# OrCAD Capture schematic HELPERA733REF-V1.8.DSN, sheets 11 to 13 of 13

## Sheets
11 07 M.2 key M Slot/4G: size B; note: M.2 key M Slot/4G
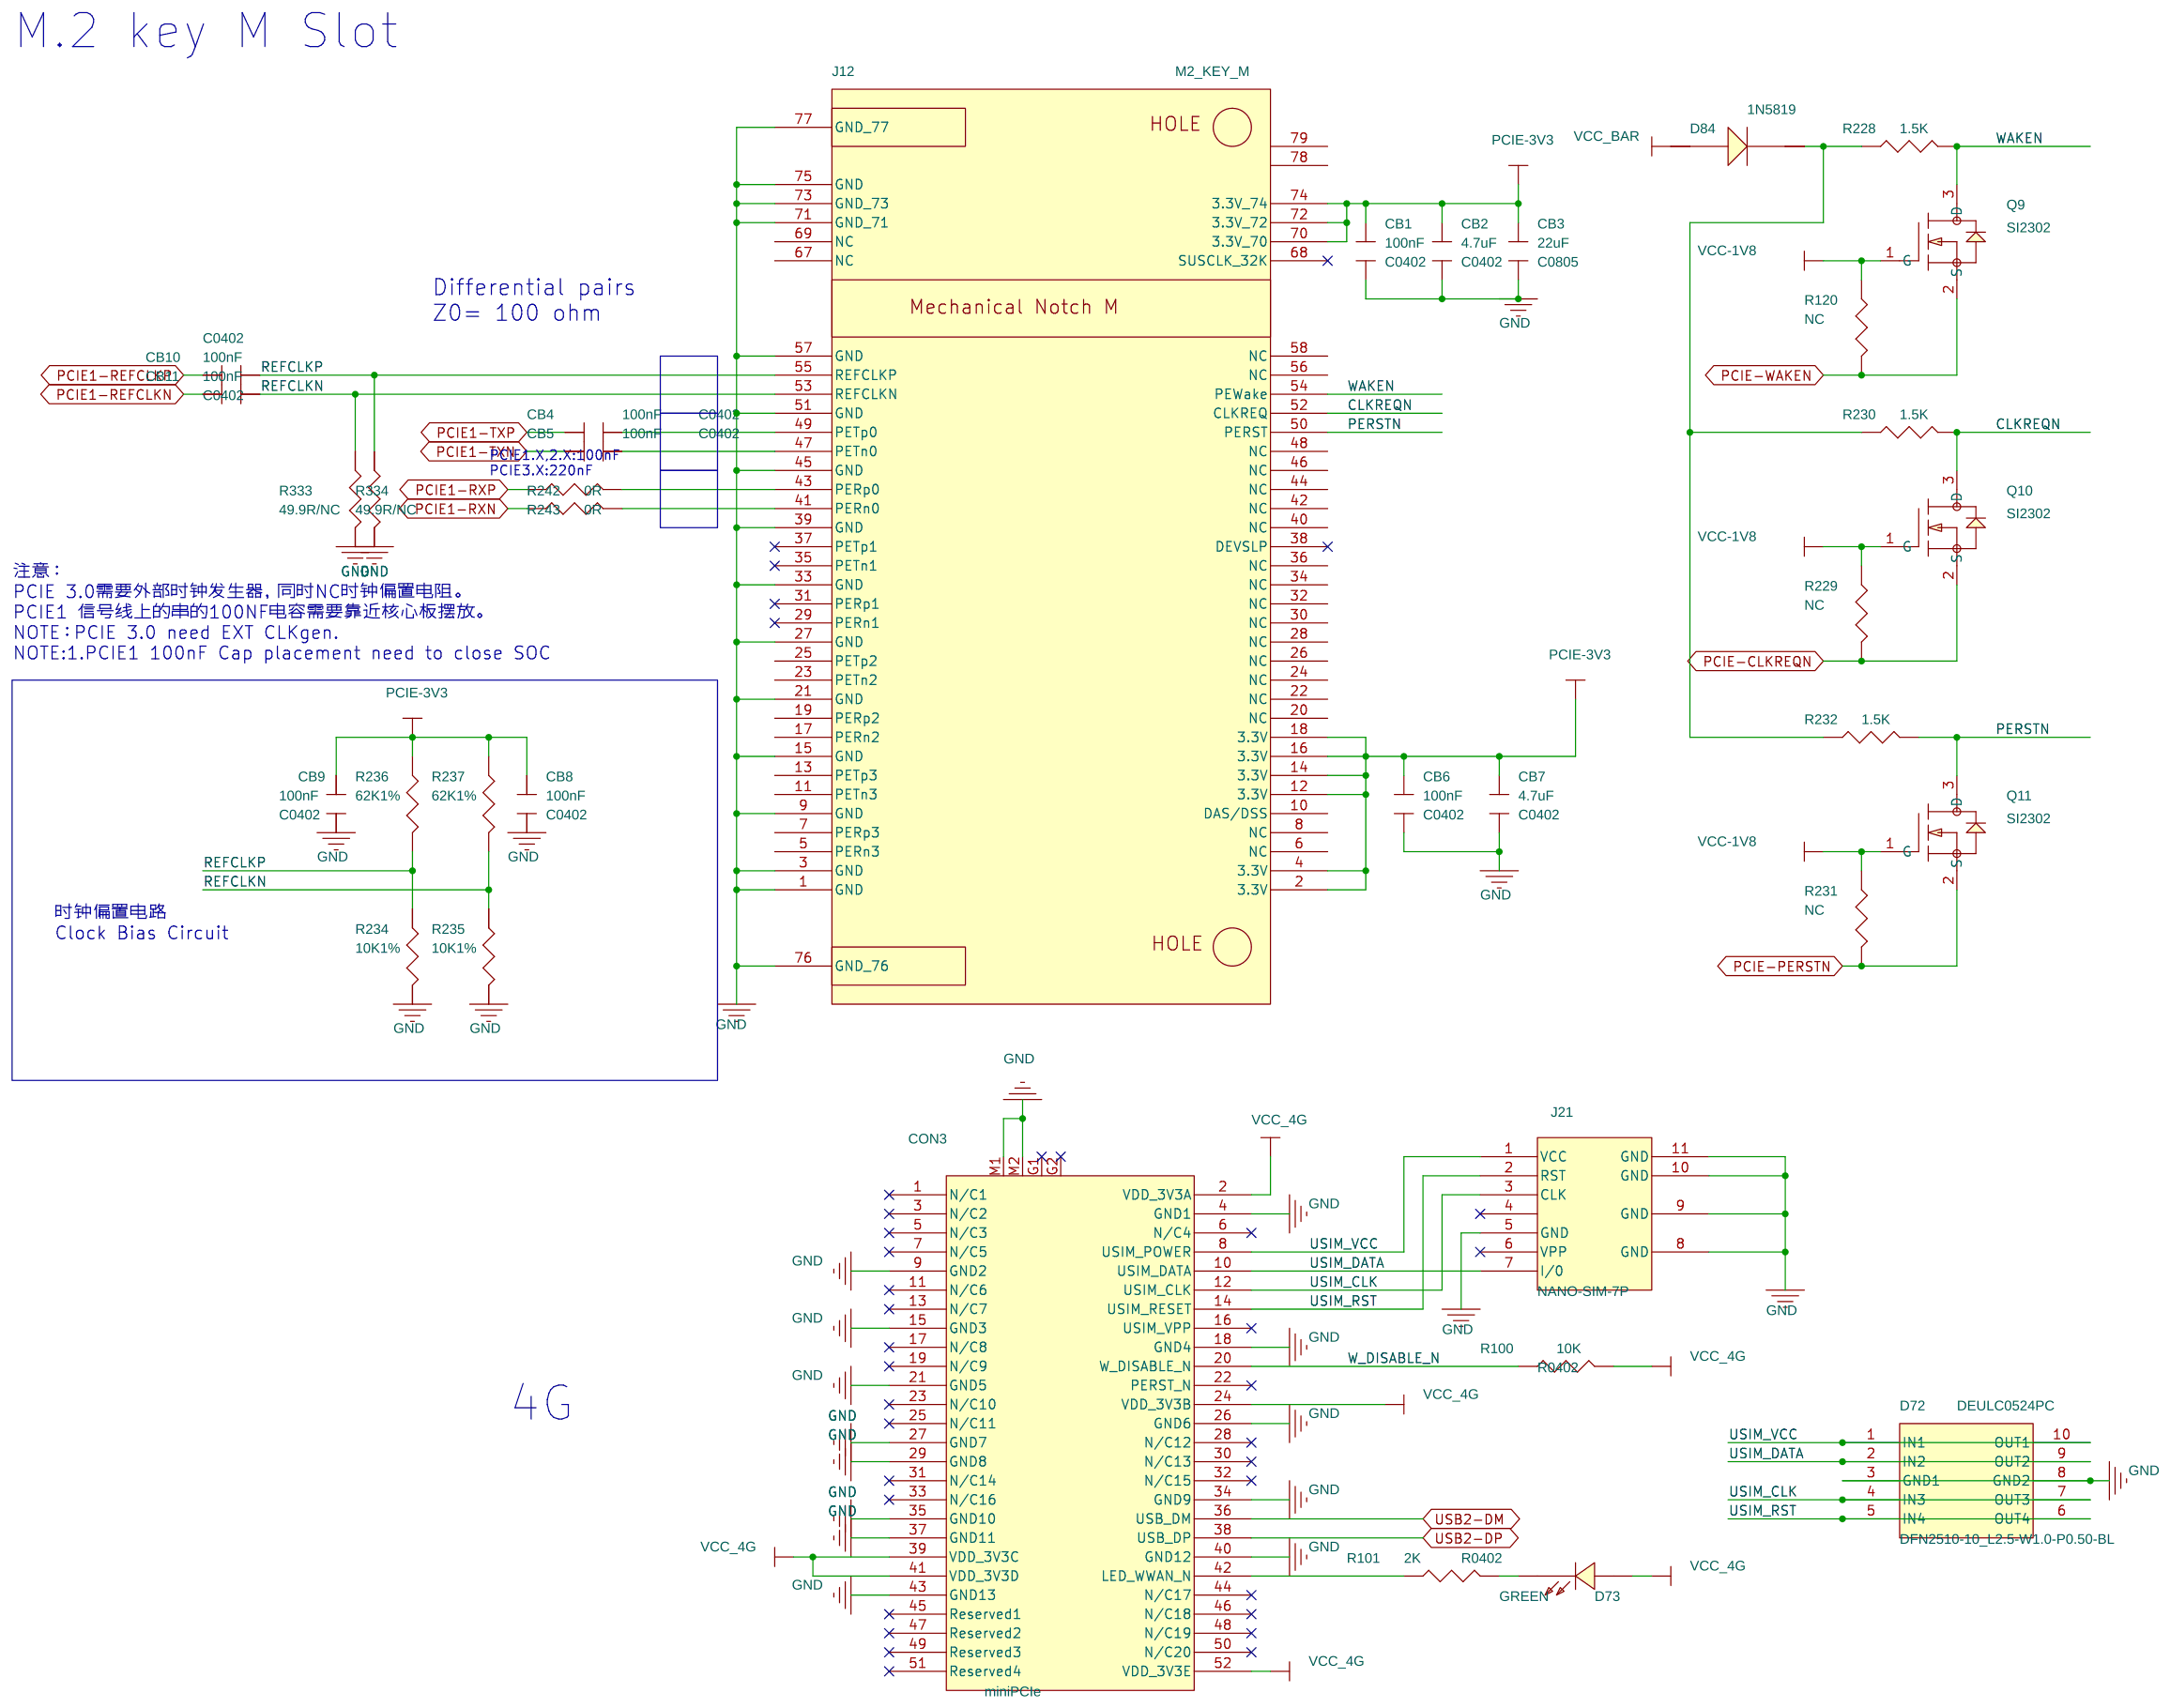
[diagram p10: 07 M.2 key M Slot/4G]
12 11 OTG/host/HUB: size B; note: OTG/host/HUB
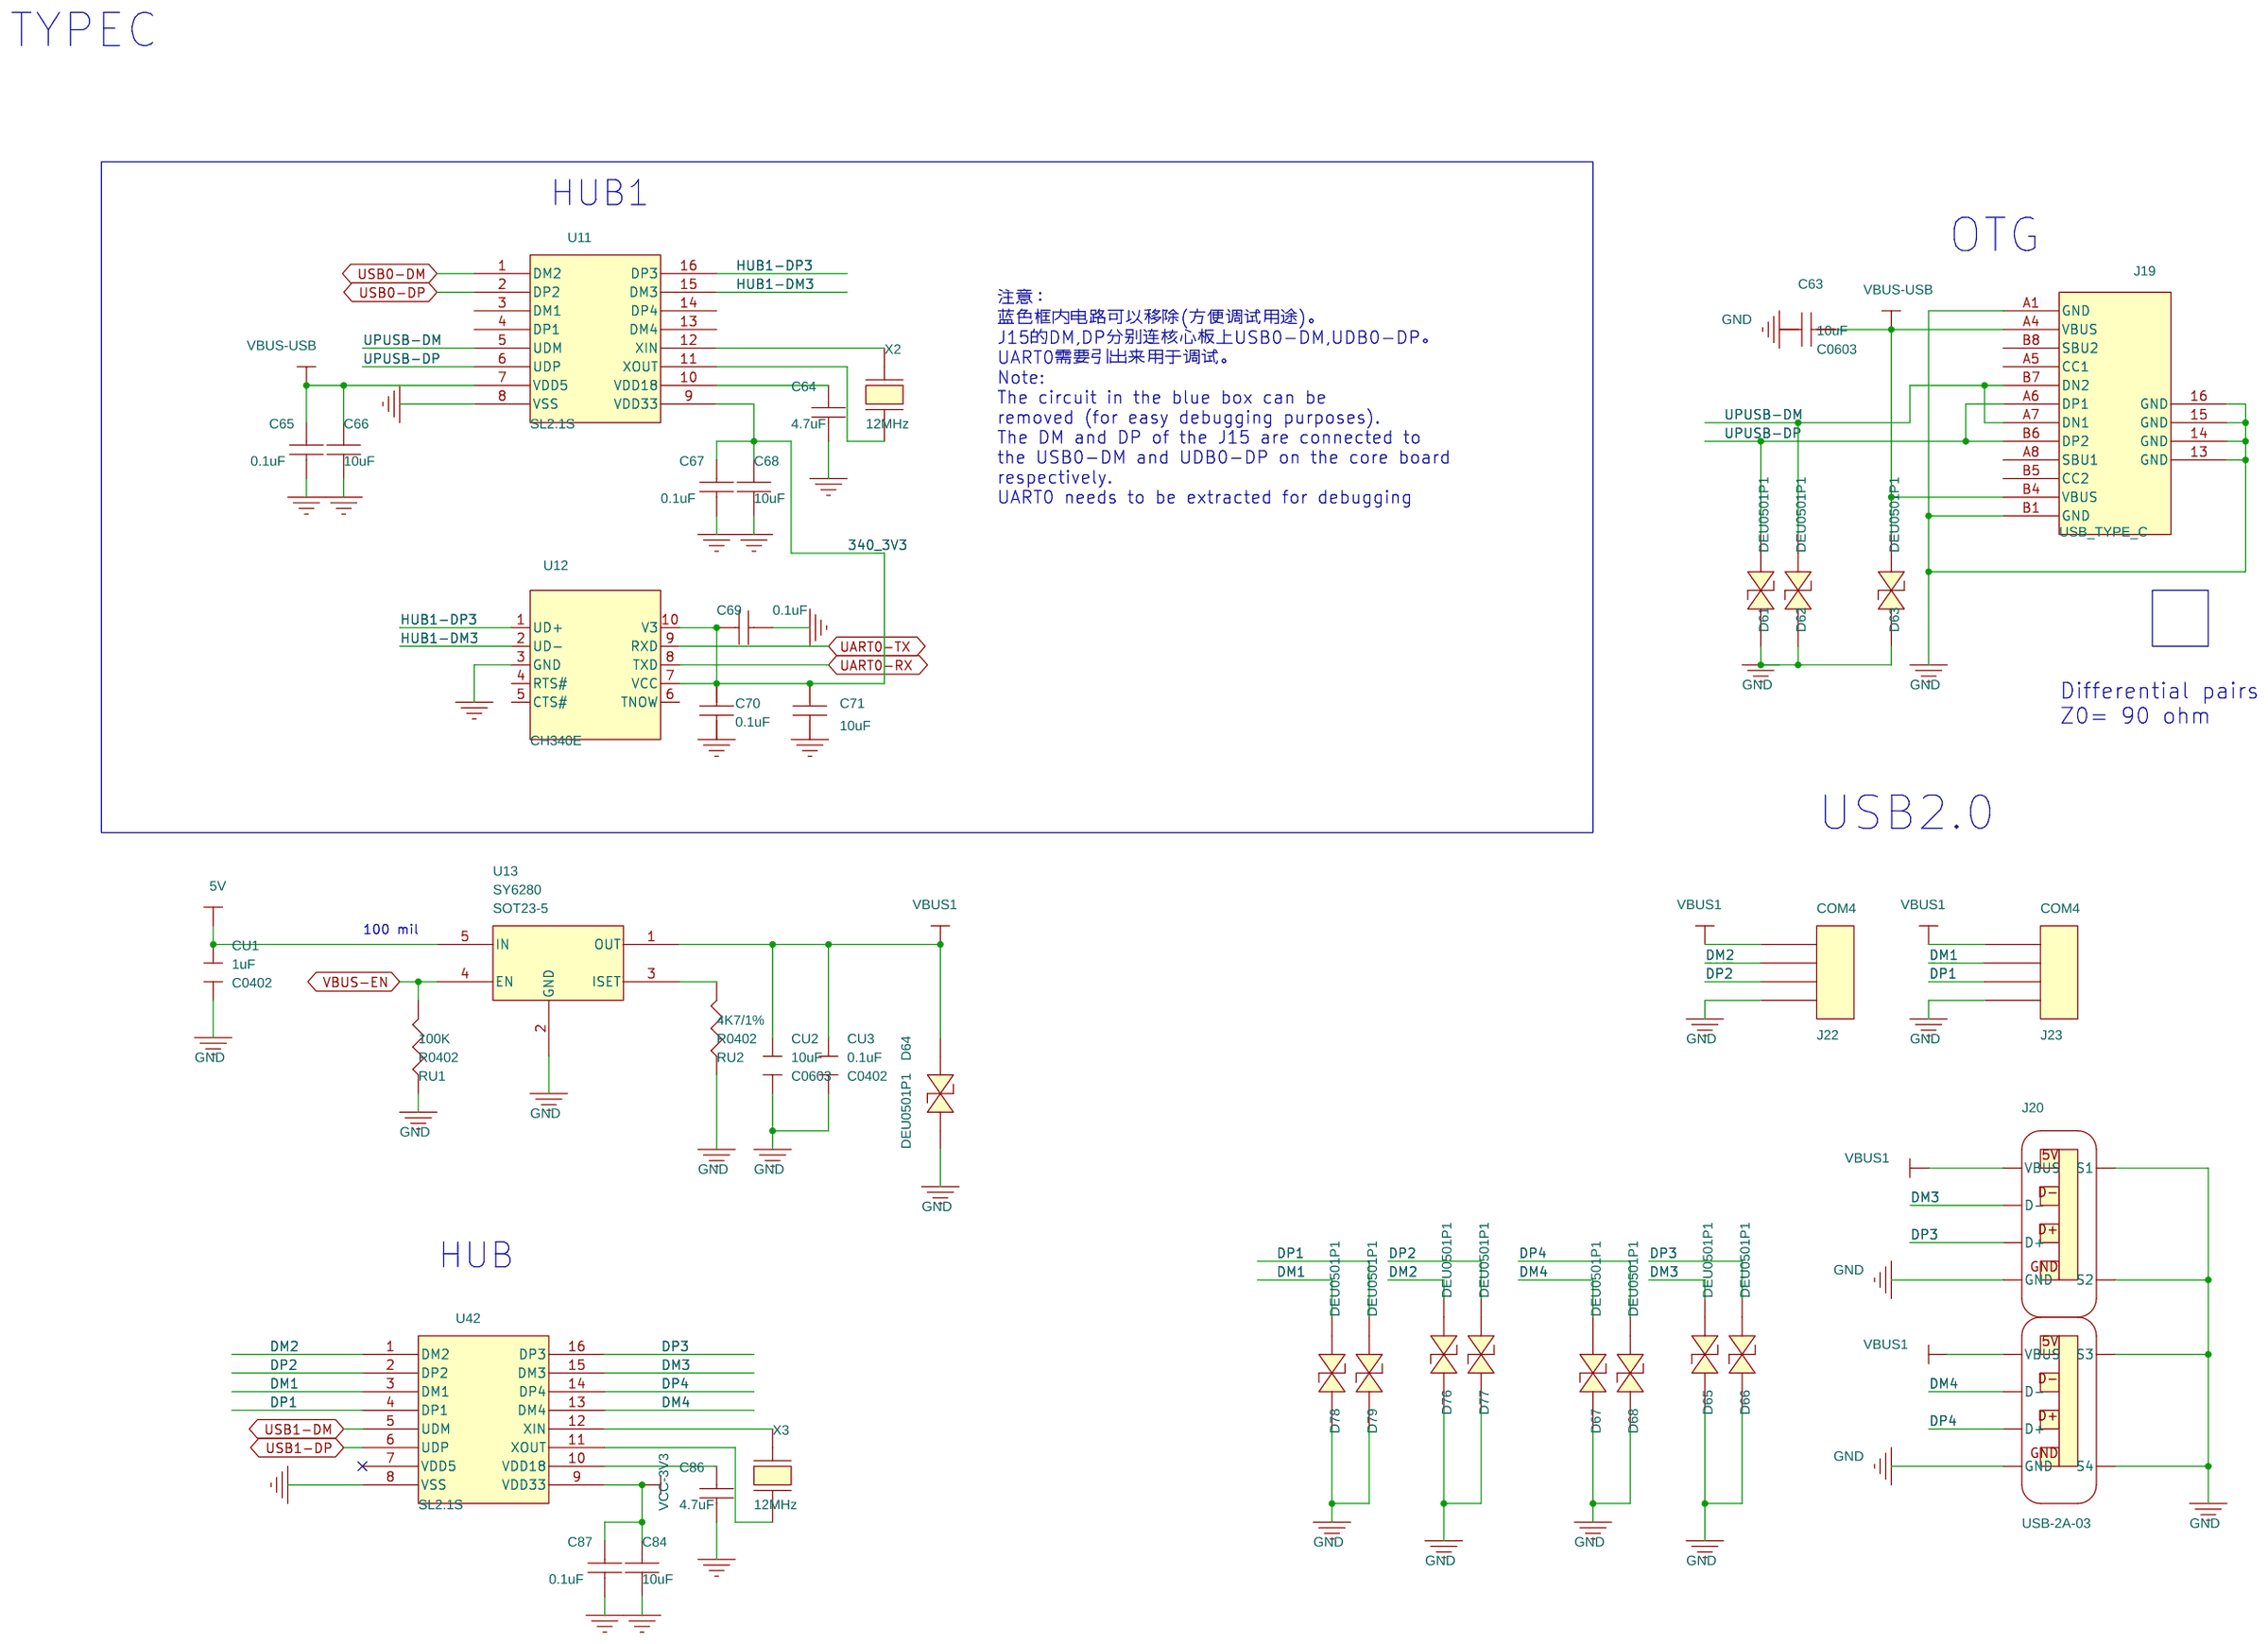
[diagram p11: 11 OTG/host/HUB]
13 06 AUDIO AC101/AC101B: size C; note: AUDIO AC101/AC101B
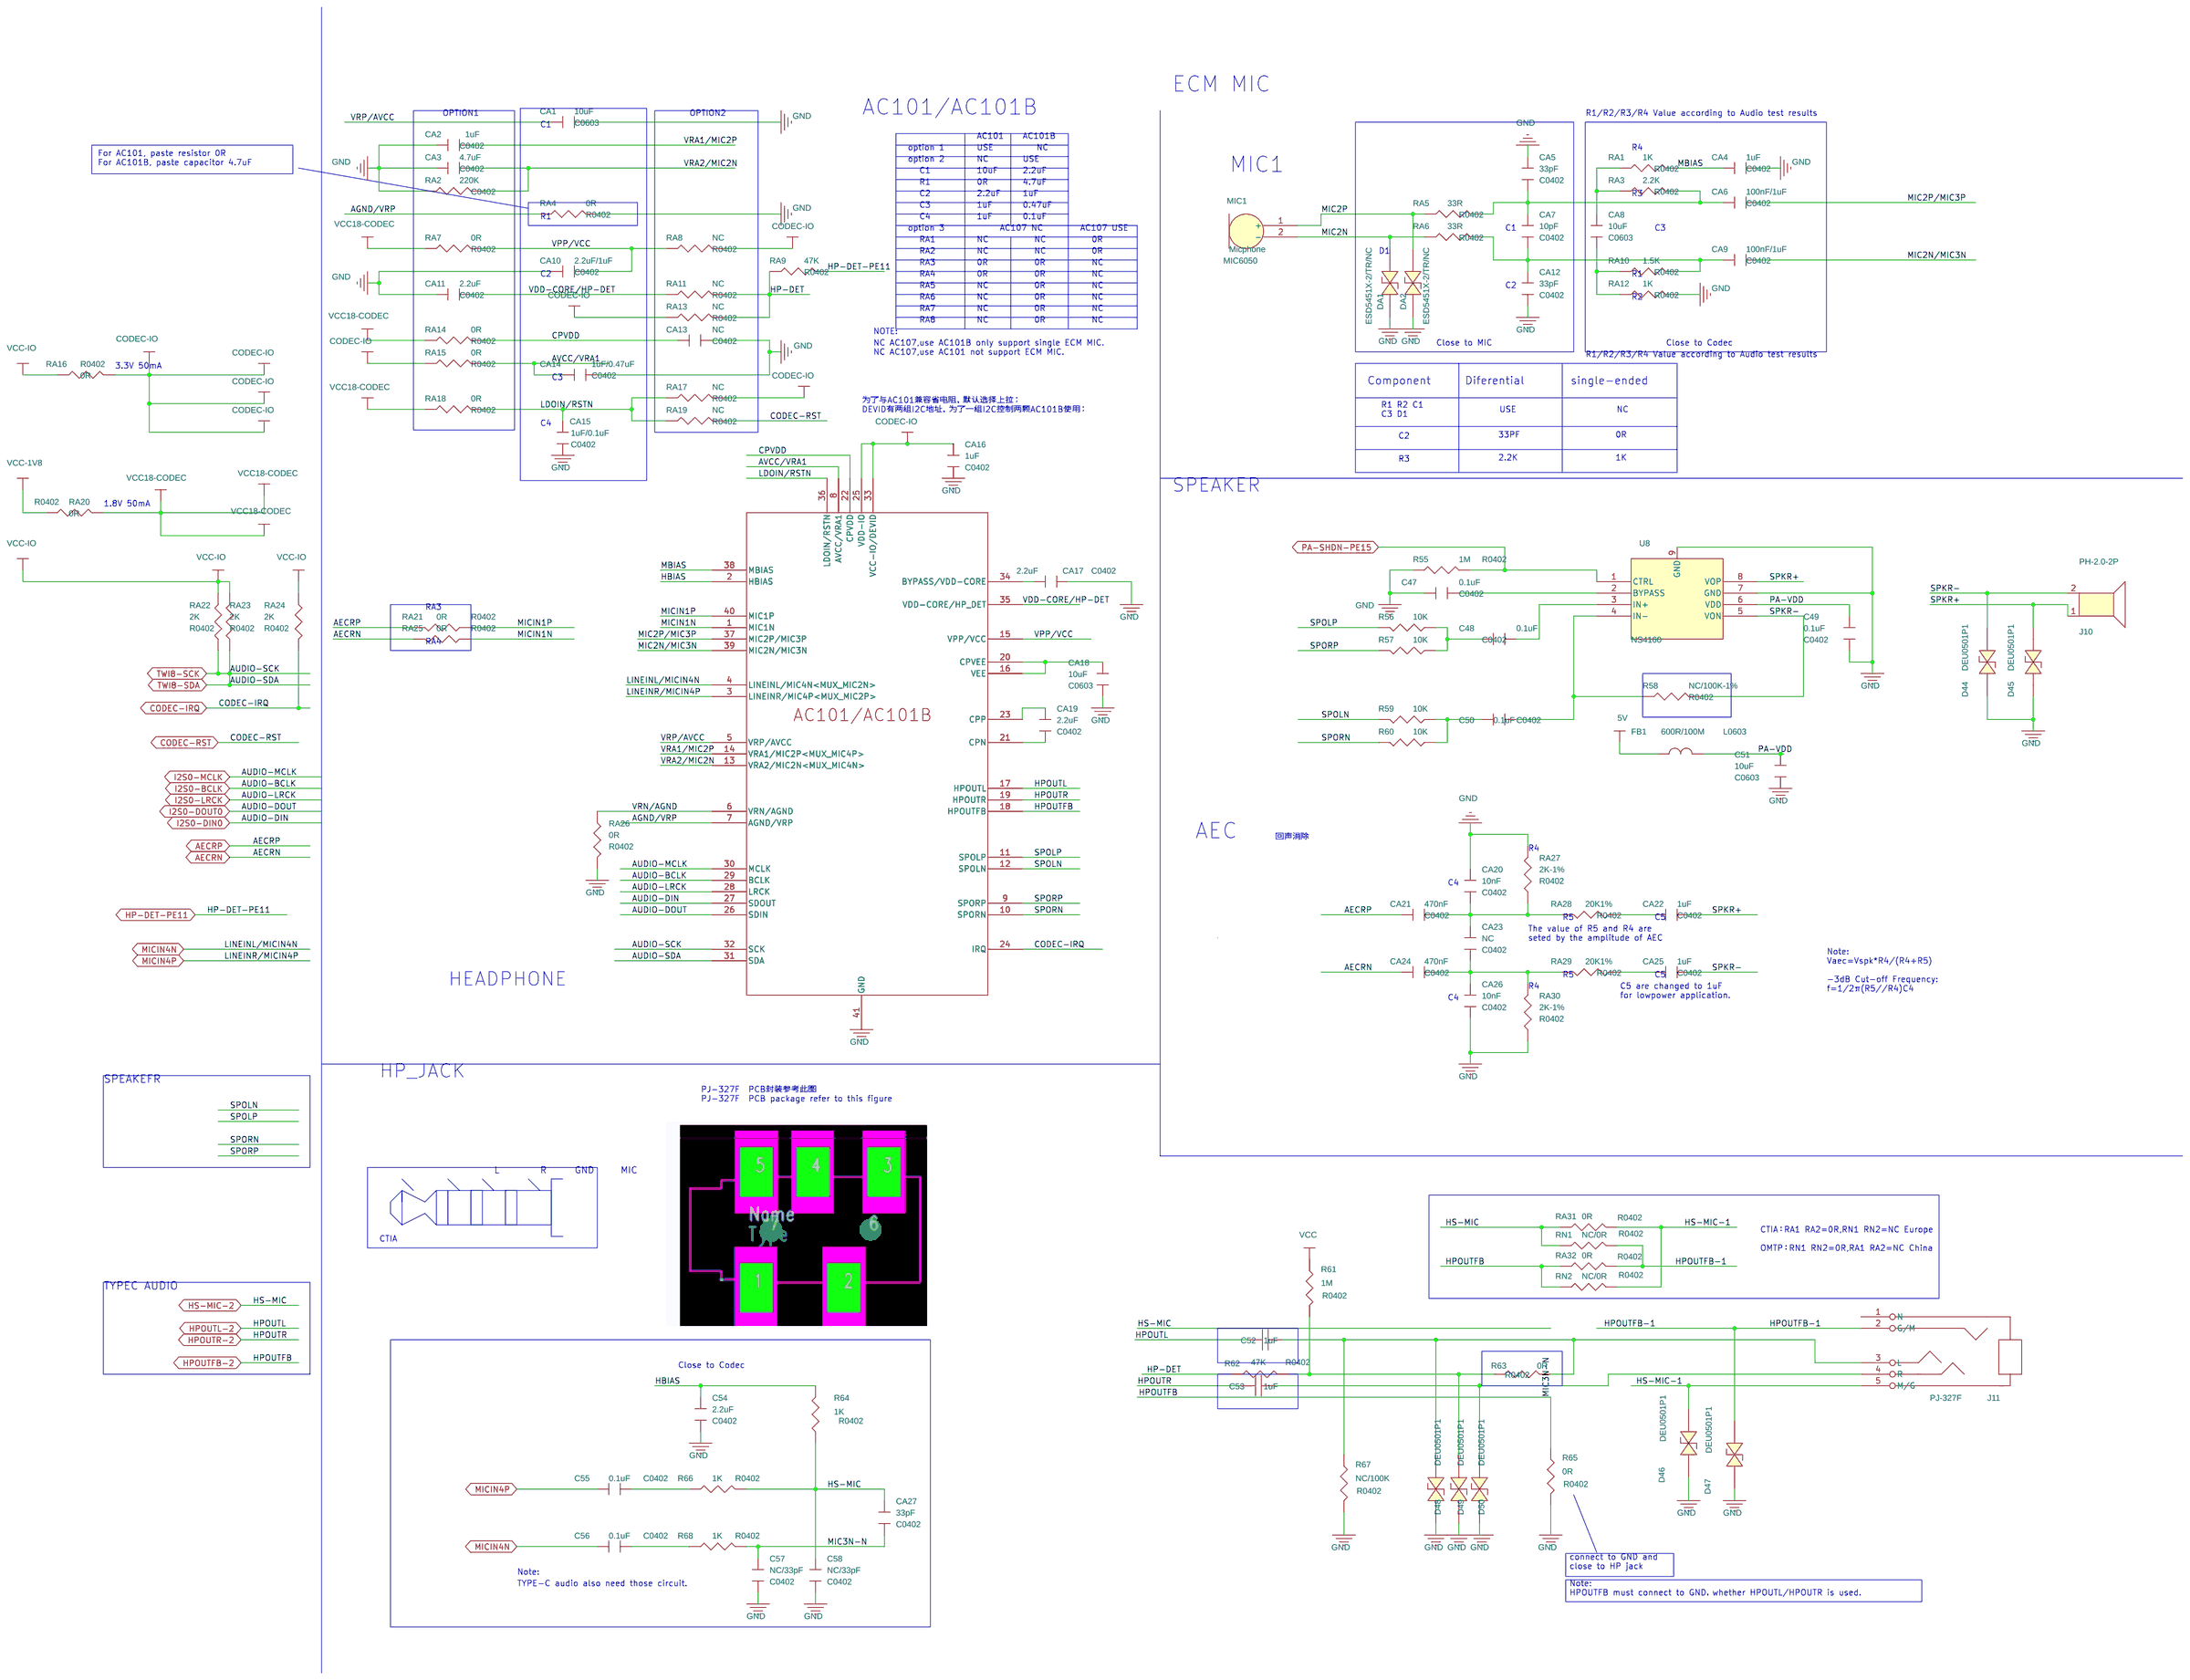
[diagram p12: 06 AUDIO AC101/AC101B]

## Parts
sheet 06 AUDIO AC101/AC101B
C47  0.1uF  [C0402]
C48  0.1uF  [C0402]
C49  0.1uF  [C0402]
C50  0.1uF  [C0402]
C51  10uF  [C0603]
C52  1uF  [C0402]
C53  1uF  [C0402]
C54  2.2uF  [C0402]
C55  0.1uF  [C0402]
C56  0.1uF  [C0402]
C57  NC/33pF  [C0402]
C58  NC/33pF  [C0402]
CA1  10uF  [C0603]
CA2  1uF  [C0402]
CA3  4.7uF  [C0402]
CA4  1uF  [C0402]
CA5  33pF  [C0402]
CA6  100nF/1uF  [C0402]
CA7  10pF  [C0402]
CA8  10uF  [C0603]
CA9  100nF/1uF  [C0402]
CA10  2.2uF/1uF  [C0402]
CA11  2.2uF  [C0402]
CA12  33pF  [C0402]
CA13  NC  [C0402]
CA14  1uF/0.47uF  [C0402]
CA15  1uF/0.1uF  [C0402]
CA16  1uF  [C0402]
CA17  2.2uF  [C0402]
CA18  10uF  [C0603]
CA19  2.2uF  [C0402]
CA20  10nF  [C0402]
CA21  470nF  [C0402]
CA22  1uF  [C0402]
CA23  NC  [C0402]
CA24  470nF  [C0402]
CA25  1uF  [C0402]
CA26  10nF  [C0402]
CA27  33pF  [C0402]
D44  DEU0501P1  [ESD0402]
D45  DEU0501P1  [ESD0402]
D46  DEU0501P1  [ESD0402]
D47  DEU0501P1  [ESD0402]
D48  DEU0501P1  [ESD0402]
D49  DEU0501P1  [ESD0402]
D50  DEU0501P1  [ESD0402]
DA1  ESD5451X-2/TR/NC  [ESD0402]
DA2  ESD5451X-2/TR/NC  [ESD0402]
FB1  600R/100M  [L0603]
J10  PH-2.0-2P  [PH-2.0-2P]
J11  PJ-327F  [PJ327F]
MIC1  Micphone  [MIC6050]
R55  1M  [R0402]
R56  10K  [R0402]
R57  10K  [R0402]
R58  NC/100K-1%  [R0402]
R59  10K  [R0402]
R60  10K  [R0402]
R61  1M  [R0402]
R62  47K  [R0402]
R63  0R  [R0402]
R64  1K  [R0402]
R65  0R  [R0402]
R66  1K  [R0402]
R67  NC/100K  [R0402]
R68  1K  [R0402]
RA1  1K  [R0402]
RA2  220K  [C0402]
RA3  2.2K  [R0402]
RA4  0R  [R0402]
RA5  33R  [R0402]
RA6  33R  [R0402]
RA7  0R  [R0402]
RA8  NC  [R0402]
RA9  47K  [R0402]
RA10  1.5K  [R0402]
RA11  NC  [R0402]
RA12  1K  [R0402]
RA13  NC  [R0402]
RA14  0R  [R0402]
RA15  0R  [R0402]
RA16  0R  [R0402]
RA17  NC  [R0402]
RA18  0R  [R0402]
RA19  NC  [R0402]
RA20  0R  [R0402]
RA21  0R  [R0402]
RA22  2K  [R0402]
RA23  2K  [R0402]
RA24  2K  [R0402]
RA25  0R  [R0402]
RA26  0R  [R0402]
RA27  2K-1%  [R0402]
RA28  20K1%  [R0402]
RA29  20K1%  [R0402]
RA30  2K-1%  [R0402]
RA31  0R  [R0402]
RA32  0R  [R0402]
RN1  NC/0R  [R0402]
RN2  NC/0R  [R0402]
U8  NS4160  [ESOP-8]
UA1  AC101  [QFN40]
sheet 07 M.2 key M Slot/4G
CB1  100nF  [C0402]
CB2  4.7uF  [C0402]
CB3  22uF  [C0805]
CB4  100nF  [C0402]
CB5  100nF  [C0402]
CB6  100nF  [C0402]
CB7  4.7uF  [C0402]
CB8  100nF  [C0402]
CB9  100nF  [C0402]
CB10  100nF  [C0402]
CB11  100nF  [C0402]
CON3  miniPCIe  [MINI_PCIEX1-52P-5.2H]
D72  DEULC0524PC  [DFN2510-10_L2.5-W1.0-P0.50-BL]
D73  GREEN  [D0603]
D84  1N5819  [SOD323]
J12  M2_KEY_M  [M.2-M-KEY]
J21  NANO-SIM-7P  [NANO-SIM-7P]
Q9  SI2302  [SOT23]
Q10  SI2302  [SOT23]
Q11  SI2302  [SOT23]
R100  10K  [R0402]
R101  2K  [R0402]
R120  NC  [R0402]
R228  1.5K  [R0402]
R229  NC  [R0402]
R230  1.5K  [R0402]
R231  NC  [R0402]
R232  1.5K  [R0402]
R234  10K1%  [R0402]
R235  10K1%  [R0402]
R236  62K1%  [R0402]
R237  62K1%  [R0402]
R242  0R  [R0402]
R243  0R  [R0402]
R333  49.9R/NC  [R0402]
R334  49.9R/NC  [R0402]
sheet 11 OTG/host/HUB
C63  10uF  [C0603]
C64  4.7uF  [C0402]
C65  0.1uF  [C0402]
C66  10uF  [C0603]
C67  0.1uF  [C0402]
C68  10uF  [C0603]
C69  0.1uF  [C0402]
C70  0.1uF  [C0402]
C71  10uF  [C0603]
C84  10uF  [C0603]
C86  4.7uF  [C0402]
C87  0.1uF  [C0402]
CU1  1uF  [C0402]
CU2  10uF  [C0603]
CU3  0.1uF  [C0402]
D61  DEU0501P1  [ESD0402]
D62  DEU0501P1  [ESD0402]
D63  DEU0501P1  [ESD0402]
D64  DEU0501P1  [ESD0402]
D65  DEU0501P1  [ESD0402]
D66  DEU0501P1  [ESD0402]
D67  DEU0501P1  [ESD0402]
D68  DEU0501P1  [ESD0402]
D76  DEU0501P1  [ESD0402]
D77  DEU0501P1  [ESD0402]
D78  DEU0501P1  [ESD0402]
D79  DEU0501P1  [ESD0402]
J19  USB_TYPE_C  [USB_C]
J20  USB-2A-03  [USB-2A-03]
J22  COM4  [PH-2.0-4P]
J23  COM4  [PH-2.0-4P]
RU1  100K  [R0402]
RU2  4K7/1%  [R0402]
U11  SL2.1S  [SSOP16_SL2.1S]
U12  CH340E  [MSOP-10]
U13  SY6280  [SOT23-5]
U42  SL2.1S  [SSOP16_SL2.1S]
X2  12MHz  [X3225]
X3  12MHz  [X3225]

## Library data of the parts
C47-C49 C51 = C-C0402
C50 = CAPACITOR_0: options: 4890-2
C52 C53 = CAP_NP_0: Status: Taiwan
C54-C58 CA4-CA7 CA9 CA12 CA20-CA27 = C-C0402: Parameter: C0402-X5R
CA1 CA2 CA10 CA11 CA16 = CAPACITOR_0: PAGE: 2; ROOM: POWER
CA3 CA13-CA15 CA17-CA19 = CAPACITOR_0: PAGE: 1; ROOM: AC100
CA8 = C-C0603: Parameter: C0402-X5R
D44 D45 = ESD9B5VL: options: 4890-1
D46-D50 = ESD9B5VL
DA1 DA2 = ESD9B5VL_0
FB1 = INDUCTOR_0_v2: RoHS BEAD/600ohm 100Mhz Z=600Ω DCR<0.2Ω 800mA SMT L0603; Package: SMT; Pin Names Rotate: TRUE; Pin Names Visible: FALSE; Pin Numbers Visible: TRUE
J10 = SPEAKER_0
J11 = PJ381-2_1
MIC1 = Micphone_0: mypage: 13
R55 R58 R61-R68 RA1 RA3 RA5 RA6 RA10 RA12 RA21 RA25 RA31 RA32 RN1 RN2 = R-R0402-5%
R56 R57 R59 R60 = RESISTOR: options: 4890-2
RA2 RA4 RA7-RA9 RA11 RA13-RA20 RA22-RA24 RA26 = R: ROOM: AC100
RA27-RA30 = R-R0603-1%
U8 = LY8006_1
UA1 = AC101&AC101B_V0_1.2
CB1-CB11 = CAPACITOR_0: PAGE: 2; ROOM: LVDS
CON3 = CON50A_5
D72 = rRClamp0524P
D73 = LED
D84 = BAS21_SOT_1
J12 = M2_KEY_B_0
J21 = SIM-7P_0
Q9-Q11 = NMOS-2N7002
R100 R101 R120 R228-R232 R234-R237 R242 R243 R333 R334 = R
C63 = CAP_NP
C64 = CAP_NP_9
C65 = CAP_NP_10
C66 = CAP_NP_7
C67 = CAP_NP_3
C68 = CAP_NP_1
C69 = CAP_NP_5
C70 = CAP_NP_2
C71 = CAP_NP_8
C84 = CAP_NP_6
C86 = CAP_NP_4
C87 = CAP_NP_11
CU1 CU3 = C-C0402: PAGE: 2; ROOM: EMMC; mypage: 08
CU2 = C-C0603
D61-D68 D76-D79 = 1_1.5KE100A: 1ST PART DESCRIPTION: WILL ESD9B5V Bidirection ESD Protection
J19 = CON12_10
J20 = USB-2A-03
J22 J23 = CON4_0
RU1 RU2 = R-R0402-5%: ROOM: EMMC; mypage: 08
U11 U42 = MW7220_QFP64_1
U12 = CH340G_1
U13 = SY6280
X2 X3 = XTAL_HC49LP_27MHz_MK2743_4

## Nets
5V: CU1.2 FB1.2 U13.5(IN) ; also on sheet 2 3 5 7 8 9
AVCC: R61.1 ; also on sheet 2 9
GND: C47.2 C49.2 C51.2 C54.1 C57.2 C58.2 C63.1 C64.2 C65.2 C66.2 C67.2 C68.2 C69.2 C70.2 C71.2 C84.2 C86.2 C87.2 CA1.1 CA2.2 CA3.1 CA4.1 CA5.1 CA10.2 CA11.2 CA12.2 CA13.2 CA14.2 CA15.2 CA16.1 CA17.2 CA18.2 CA20.1 CA26.2 CB1.1 CB2.1 CB3.1 CB6.1 CB7.1 CB8.1 CB9.1 CON3.4(GND1) CON3.9(GND2) CON3.15(GND3) CON3.18(GND4) CON3.21(GND5) CON3.26(GND6) CON3.27(GND7) CON3.29(GND8) CON3.34(GND9) CON3.35(GND10) CON3.37(GND11) CON3.40(GND12) CON3.43(GND13) CON3.M1 CON3.M2 CU1.1 CU2.1 CU3.1 D44.1(ANODE) D45.1(ANODE) D46.1(ANODE) D47.1(ANODE) D48.1(ANODE) D49.1(ANODE) D50.1(ANODE) D61.2(CATHODE) D62.2(CATHODE) D63.2(CATHODE) D64.1(ANODE) D65.2(CATHODE) D66.2(CATHODE) D67.2(CATHODE) D68.2(CATHODE) D72.3(GND1) D72.8(GND2) D76.2(CATHODE) D77.2(CATHODE) D78.2(CATHODE) D79.2(CATHODE) DA1.1(ANODE) DA2.1(ANODE) J12.1(GND) J12.3(GND) J12.9(GND) J12.15(GND) J12.21(GND) J12.27(GND) J12.33(GND) J12.39(GND) J12.45(GND) J12.51(GND) J12.57(GND) J12.71(GND) J12.73(GND) J12.75(GND) J12.76(GND) J12.77(GND) J19.13(GND) J19.14(GND) J19.15(GND) J19.16(GND) J19.A1(GND) J19.B1(GND) J20.4(GND) J20.8(GND) J20.9(S1) J20.10(S2) J20.11(S3) J20.12(S4) J21.5(GND) J21.8(GND) J21.9(GND) J21.10(GND) J21.11(GND) J22.1 J23.1 R55.1 R65.2 R67.2 R234.2 R235.2 R333.2 R334.2 RA2.1 RA4.2 RA12.2 RA26.2 RA27.2 RA30.1 RU1.1 RU2.1 U8.7(GND) U8.9(GND) U11.8(VSS) U12.3(GND) U13.2(GND) U42.8(VSS) UA1.41(GND) ; also on sheet 2 3 4 5 6 7 8 9 10
VBUS1: CU2.2 CU3.2 D64.2(CATHODE) J20.1(VBUS) J20.5(VBUS) J22.4 J23.4 U13.1(OUT)
VBUS-EN: RU1.2 U13.4(EN) ; also on sheet 2
VBUS-USB: C63.2 C65.1 C66.1 D63.1(ANODE) J19.A4(VBUS) J19.B4(VBUS) U11.7(VDD5)
VCC-1V8: Q9.1(G) Q10.1(G) Q11.1(G) R120.1 R229.1 R231.1 RA20.1 ; also on sheet 3 5 10
VCC-3V3: C84.1 C87.1 RA16.1 RA22.2 RA23.2 RA24.1 U42.9(VDD33) ; also on sheet 3 5 6 7 8 9 10
VCC_4G: CON3.2(VDD_3V3A) CON3.24(VDD_3V3B) CON3.39(VDD_3V3C) CON3.41(VDD_3V3D) CON3.52(VDD_3V3E) D73.1(ANODE) R100.2 ; also on sheet 3
VPP/VCC: CA10.1 RA7.2 RA8.1 UA1.15(VPP/VCC)
VRN/AGND: RA26.1 UA1.6(VRN/AGND)
VRP/AVCC: CA1.2 UA1.5(VRP/AVCC)
340_3V3: C67.1 C68.1 C69.1 C70.1 C71.1 U11.9(VDD33) U12.7(VCC) U12.10(V3)
AECRN: CA24.2 RA25.1
AECRP: CA21.2 RA21.1
AGND/VRP: RA4.1 UA1.7(AGND/VRP)
AVCC/VRA1: CA14.1 RA15.2 UA1.8(AVCC/VRA1)
CLKREQN: J12.52(CLKREQ) Q10.3(D) R230.2
CODEC-AVCC: CA16.2 RA8.2 RA13.1 RA15.1 RA16.2 RA17.2 UA1.25(VDD-IO) UA1.33(VCC-IO/DEVID)
CODEC-CPVDD: RA7.1 RA14.1 RA18.1 RA20.2
CODEC-IRQ: RA24.2 UA1.24(IRQ) ; also on sheet 2
CODEC-RST: RA19.2 ; also on sheet 2
CPVDD: CA13.1 RA14.2 UA1.22(CPVDD)
DM1: D78.1(ANODE) J23.3 U42.3(DM1)
DM2: D76.1(ANODE) J22.3 U42.1(DM2)
DM3: D65.1(ANODE) J20.2(D-) U42.15(DM3)
DM4: D67.1(ANODE) J20.6(D-) U42.13(DM4)
DP1: D79.1(ANODE) J23.2 U42.4(DP1)
DP2: D77.1(ANODE) J22.2 U42.2(DP2)
DP3: D66.1(ANODE) J20.3(D+) U42.16(DP3)
DP4: D68.1(ANODE) J20.7(D+) U42.14(DP4)
HBIAS: C54.2 R64.2 UA1.2(HBIAS)
HP-DET: R62.1 RA9.1 RA11.2 RA13.2
HP-DET-PE11: RA9.2 ; also on sheet 2
HPOUTFB-1: D47.2(CATHODE) J11.2(G/M) RA32.2 RN1.2
HPOUTFB-2: C57.1 CA27.2 R65.1 R68.2 RA32.1 RN2.1 UA1.18(HPOUTFB)
HPOUTL-2: C52.2 UA1.17(HPOUTL)
HPOUTR-2: C53.2 UA1.19(HPOUTR)
HS-MIC-1: D46.2(CATHODE) J11.5(M/G) RA31.2 RN2.2
HS-MIC-2: C58.1 CA27.1 R64.1 R66.2 RA31.1 RN1.1
HUB1-DM3: U11.15(DM3) U12.2(UD-)
HUB1-DP3: U11.16(DP3) U12.1(UD+)
I2S0-BCLK: UA1.29(BCLK) ; also on sheet 2
I2S0-DIN0: UA1.27(SDOUT) ; also on sheet 2
I2S0-DOUT0: UA1.26(SDIN) ; also on sheet 2
I2S0-LRCK: UA1.28(LRCK) ; also on sheet 2
I2S0-MCLK: UA1.30(MCLK) ; also on sheet 2
LDOIN/RSTN: CA15.1 RA17.1 RA18.2 RA19.1 UA1.36(LDOIN/RSTN)
MBIAS: CA4.2 RA1.2 UA1.38(MBIAS)
MIC2N: DA1.2(CATHODE) MIC1.2(-) RA6.1
MIC2N/MIC3N: CA9.1 UA1.39(MIC2N/MIC3N)
MIC2P: DA2.2(CATHODE) MIC1.1(+) RA5.1
MIC2P/MIC3P: CA6.1 UA1.37(MIC2P/MIC3P)
MICIN1N: RA25.2 UA1.1(MIC1N)
MICIN1P: RA21.2 UA1.40(MIC1P)
MICIN4N: C56.1 UA1.4(LINEINL/MIC4N<MUX_MIC2N>)
MICIN4P: C55.1 UA1.3(LINEINR/MIC4P<MUX_MIC2P>)
PA-SHDN-PE15: R55.2 U8.1(CTRL) ; also on sheet 2
PA-VDD: C49.1 C51.1 FB1.1 U8.6(VDD)
PCIE1-REFCLKN: CB11.1 ; also on sheet 2
PCIE1-REFCLKP: CB10.1 ; also on sheet 2
PCIE1-RXN: R243.1 ; also on sheet 2
PCIE1-RXP: R242.1 ; also on sheet 2
PCIE1-TXN: CB5.1 ; also on sheet 2
PCIE1-TXP: CB4.1 ; also on sheet 2
PCIE-3V3: CB1.2 CB2.2 CB3.2 CB6.2 CB7.2 CB8.2 CB9.2 D84.1(ANODE) J12.2(3.3V) J12.4(3.3V) J12.12(3.3V) J12.14(3.3V) J12.16(3.3V) J12.18(3.3V) J12.70(3.3V) J12.72(3.3V) J12.74(3.3V) R236.1 R237.1 ; also on sheet 3 5
PCIE-CLKREQN: Q10.2(S) R229.2 ; also on sheet 2
PCIE-PERSTN: Q11.2(S) R231.2 ; also on sheet 2
PCIE-WAKEN: Q9.2(S) R120.2 ; also on sheet 2
PERSTN: J12.50(PERST) Q11.3(D) R232.2
REFCLKN: CB11.2 J12.53(REFCLKN) R235.1 R237.2 R333.1
REFCLKP: CB10.2 J12.55(REFCLKP) R234.1 R236.2 R334.1
SPKR+: CA22.1 D45.2(CATHODE) J10.1 U8.8(VOP)
SPKR-: CA25.1 D44.2(CATHODE) J10.2 R58.2 U8.5(VON)
SPOLN: R59.1 UA1.12(SPOLN)
SPOLP: R56.1 UA1.11(SPOLP)
SPORN: R60.1 UA1.10(SPORN)
SPORP: R57.1 UA1.9(SPORP)
TWI8-SCK: RA22.1 UA1.32(SCK) ; also on sheet 2
TWI8-SDA: RA23.1 UA1.31(SDA) ; also on sheet 2
UART0-RX: U12.8(TXD) ; also on sheet 2
UART0-TX: U12.9(RXD) ; also on sheet 2
UPUSB-DM: D62.1(ANODE) J19.A7(DN1) J19.B7(DN2) U11.5(UDM)
UPUSB-DP: D61.1(ANODE) J19.A6(DP1) J19.B6(DP2) U11.6(UDP)
USB0-DM: U11.1(DM2) ; also on sheet 2
USB0-DP: U11.2(DP2) ; also on sheet 2
USB1-DM: U42.5(UDM) ; also on sheet 2
USB1-DP: U42.6(UDP) ; also on sheet 2
USB2-DM: CON3.36(USB_DM) ; also on sheet 2
USB2-DP: CON3.38(USB_DP) ; also on sheet 2
USIM_CLK: CON3.12(USIM_CLK) D72.4(IN3) D72.7(OUT3) J21.3(CLK)
USIM_DATA: CON3.10(USIM_DATA) D72.2(IN2) D72.9(OUT2) J21.7(I/0)
USIM_RST: CON3.14(USIM_RESET) D72.5(IN4) D72.6(OUT4) J21.2(RST)
USIM_VCC: CON3.8(USIM_POWER) D72.1(IN1) D72.10(OUT1) J21.1(VCC)
VDD-CORE/HP-DET: CA11.1 RA11.1 UA1.35(VDD-CORE/HP_DET)
VRA1/MIC2P: CA2.1 UA1.14(VRA1/MIC2P<MUX_MIC4P>)
VRA2/MIC2N: CA3.2 RA2.2 UA1.13(VRA2/MIC2N<MUX_MIC4N>)
W_DISABLE_N: CON3.20(W_DISABLE_N) R100.1
WAKEN: J12.54(PEWake) Q9.3(D) R228.2
N17819196: CA18.1 UA1.16(VEE) UA1.20(CPVEE)
N17819206: CA19.1 UA1.23(CPP)
N17819214: CA19.2 UA1.21(CPN)
N17819230: CA17.1 UA1.34(BYPASS/VDD-CORE)
N17819689: CA5.2 CA6.2 CA7.1 RA3.2 RA5.2
N17819691: CA7.2 CA9.2 CA12.1 RA6.2 RA10.2
N17819723: CA8.2 RA10.1 RA12.1
N17819725: CA8.1 RA1.1 RA3.1
N17838408: C55.2 R66.1
N17838410: C56.2 R68.1
N17838457: C52.1 D48.2(CATHODE) J11.3(L) R63.2 R67.1
N17838500: C53.1 D50.2(CATHODE) J11.4(R)
N17838683: D49.2(CATHODE) R61.2 R62.2 R63.1
N17845378: C48.2 R56.2 R57.2
N17845396: C50.2 R59.2 R60.2
N17845478: C48.1 U8.3(IN+)
N17845505: C50.1 R58.1 U8.4(IN-)
N17845570: C47.1 U8.2(BYPASS)
N17874598: CA20.2 CA21.1 CA23.1 RA27.1 RA28.2
N17874616: CA23.2 CA24.1 CA26.1 RA29.2 RA30.2
N17874634: CA22.2 RA28.1
N17874636: CA25.2 RA29.1
N17963617: RU2.2 U13.3(ISET)
N17967469: U11.12(XIN) X2.1
N17967471: U11.11(XOUT) X2.3
N17967477: C64.1 U11.10(VDD18)
N18103307: CB4.2 J12.49(PETp0)
N18103321: CB5.2 J12.47(PETn0)
N18142204: CON3.42(LED_WWAN_N) R101.1
N18142206: D73.2(CATHODE) R101.2
N18142901: U42.12(XIN) X3.1
N18142903: U42.11(XOUT) X3.3
N18142917: C86.1 U42.10(VDD18)
N18193662: D84.2(CATHODE) R228.1 R230.1 R232.1
N18257684: J12.43(PERp0) R242.2
N18257704: J12.41(PERn0) R243.2

Not connected (* = marked no-connect by the designer): CON3 1(N/C1)* 3(N/C2)* 5(N/C3)* 6(N/C4)* 7(N/C5)* 11(N/C6)* 13(N/C7)* 16(USIM_VPP)* 17(N/C8)* 19(N/C9)* 22(PERST_N)* 23(N/C10)* 25(N/C11)* 28(N/C12)* 30(N/C13)* 31(N/C14)* 32(N/C15)* 33(N/C16)* 44(N/C17)* 45(Reserved1)* 46(N/C18)* 47(Reserved2)* 48(N/C19)* 49(Reserved3)* 50(N/C20)* 51(Reserved4)* G1* G2*; J11 1(N); J12 5(PERn3) 6(NC) 7(PERp3) 8(NC) 10(DAS/DSS) 11(PETn3) 13(PETp3) 17(PERn2) 19(PERp2) 20(NC) 22(NC) 23(PETn2) 24(NC) 25(PETp2) 26(NC) 28(NC) 29(PERn1)* 30(NC) 31(PERp1)* 32(NC) 34(NC) 35(PETn1)* 36(NC) 37(PETp1)* 38(DEVSLP)* 40(NC) 42(NC) 44(NC) 46(NC) 48(NC) 56(NC) 58(NC) 67(NC) 68(SUSCLK_32K)* 69(NC) 78 79; J19 A5(CC1) A8(SBU1) B5(CC2) B8(SBU2); J21 4* 6(VPP)*; U11 3(DM1) 4(DP1) 13(DM4) 14(DP4); U12 4(RTS#) 5(CTS#) 6(TNOW); U42 7(VDD5)*

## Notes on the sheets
sheet 11
- M.2 key M Slot
- Differential pairs
  Z0= 100 ohm
- PCIE1.X,2.X:100nF
  PCIE3.X:220nF
- 注意：
  PCIE 3.0需要外部时钟发生器，同时NC时钟偏置电阻。
  PCIE1 信号线上的串的100NF电容需要靠近核心板摆放。
  NOTE：PCIE 3.0 need EXT CLKgen.
  NOTE:1.PCIE1 100nF Cap placement need to close SOC
- 时钟偏置电路
  Clock Bias Circuit
- 4G
sheet 12
- TYPEC
- HUB1
- OTG
- 注意：
  蓝色框内电路可以移除(方便调试用途)。
  J15的DM,DP分别连核心板上USB0-DM,UDB0-DP。
  UART0需要引出来用于调试。
  Note:
  The circuit in the blue box can be
  removed (for easy debugging purposes).
  The DM and DP of the J15 are connected to
  the USB0-DM and UDB0-DP on the core board
  respectively.
  UART0 needs to be extracted for debugging
- Differential pairs
  Z0= 90 ohm
- USB2.0
- 100 mil
- HUB
sheet 13
- ECM MIC
- AC101/AC101B
- OPTION1
- OPTION2
- R1/R2/R3/R4 Value according to Audio test results
- C1
- AC101
- AC101B
- option 1
- USE
- NC
- R4
- For AC101, paste resistor 0R
  For AC101B, paste capacitor 4.7uF
- option 2
- NC
- USE
- MIC1
- C1
- 10uF
- 2.2uF
- R1
- 0R
- 4.7uF
- C2
- C3
- 1uF
- 2.2uF
- 0.47uF
- 1uF
- R3
- R1
- C4
- 1uF
- 0.1uF
- option 3
- AC107 NC
- AC107 USE
- C1
- C3
- RA1
- NC
- NC
- 0R
- RA2
- NC
- NC
- 0R
- D1
- RA3
- 0R
- 0R
- NC
- C2
- RA4
- RA5
- 0R
- NC
- 0R
- 0R
- NC
- NC
- C2
- R1
- RA6
- NC
- 0R
- NC
- R2
- RA7
- NC
- 0R
- NC
- RA8
- NC
- 0R
- NC
- NOTE:
- NC AC107,use AC101B only support single ECM MIC.
  NC AC107,use AC101 not support ECM MIC.
- Close to MIC
- R1/R2/R3/R4 Value according to Audio test results
- Close to Codec
- 3.3V 50mA
- C3
- Component
- Diferential
- single-ended
- 为了与AC101兼容省电阻，默认选择上拉；
  DEVID有两组I2C地址，为了一组I2C控制两颗AC101B使用；
- R1 R2 C1
  C3 D1
- USE
- NC
- C4
- C2
- 33PF
- 0R
- R3
- 2.2K
- 1K
- SPEAKER
- 1.8V 50mA
- RA3
- RA4
- AEC
- 回声消除
- R4
- C4
- R5
- C5
- The value of R5 and R4 are
  seted by the amplitude of AEC
- Note:
  Vaec=Vspk*R4/(R4+R5)
  -3dB Cut-off Frequency:
  f=1/2π(R5//R4)C4
- HEADPHONE
- R5
- C5
- R4
- C5 are changed to 1uF
  for lowpower application.
- C4
- HP_JACK
- SPEAKEFR
- PJ-327F  PCB封装参考此图
  PJ-327F  PCB package refer to this figure
- L
- R
- GND
- MIC
- CTIA：RA1 RA2=0R,RN1 RN2=NC Europe
  OMTP：RN1 RN2=0R,RA1 RA2=NC China
- CTIA
- TYPEC AUDIO
- Close to Codec
- connect to GND and
  close to HP jack
- Note:
- TYPE-C audio also need those circuit.
- Note:
  HPOUTFB must connect to GND，whether HPOUTL/HPOUTR is used.
